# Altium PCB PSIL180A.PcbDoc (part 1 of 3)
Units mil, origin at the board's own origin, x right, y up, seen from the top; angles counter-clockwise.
Board outline 4350 x 4350 mil, 4 copper layers (L1-Top Layer, L2-GND, L3-GND/SIG, L4-Bottom Layer), stack 60.02 mil thick; 134 components, 52 nets, 287 pads, 1110 vias.
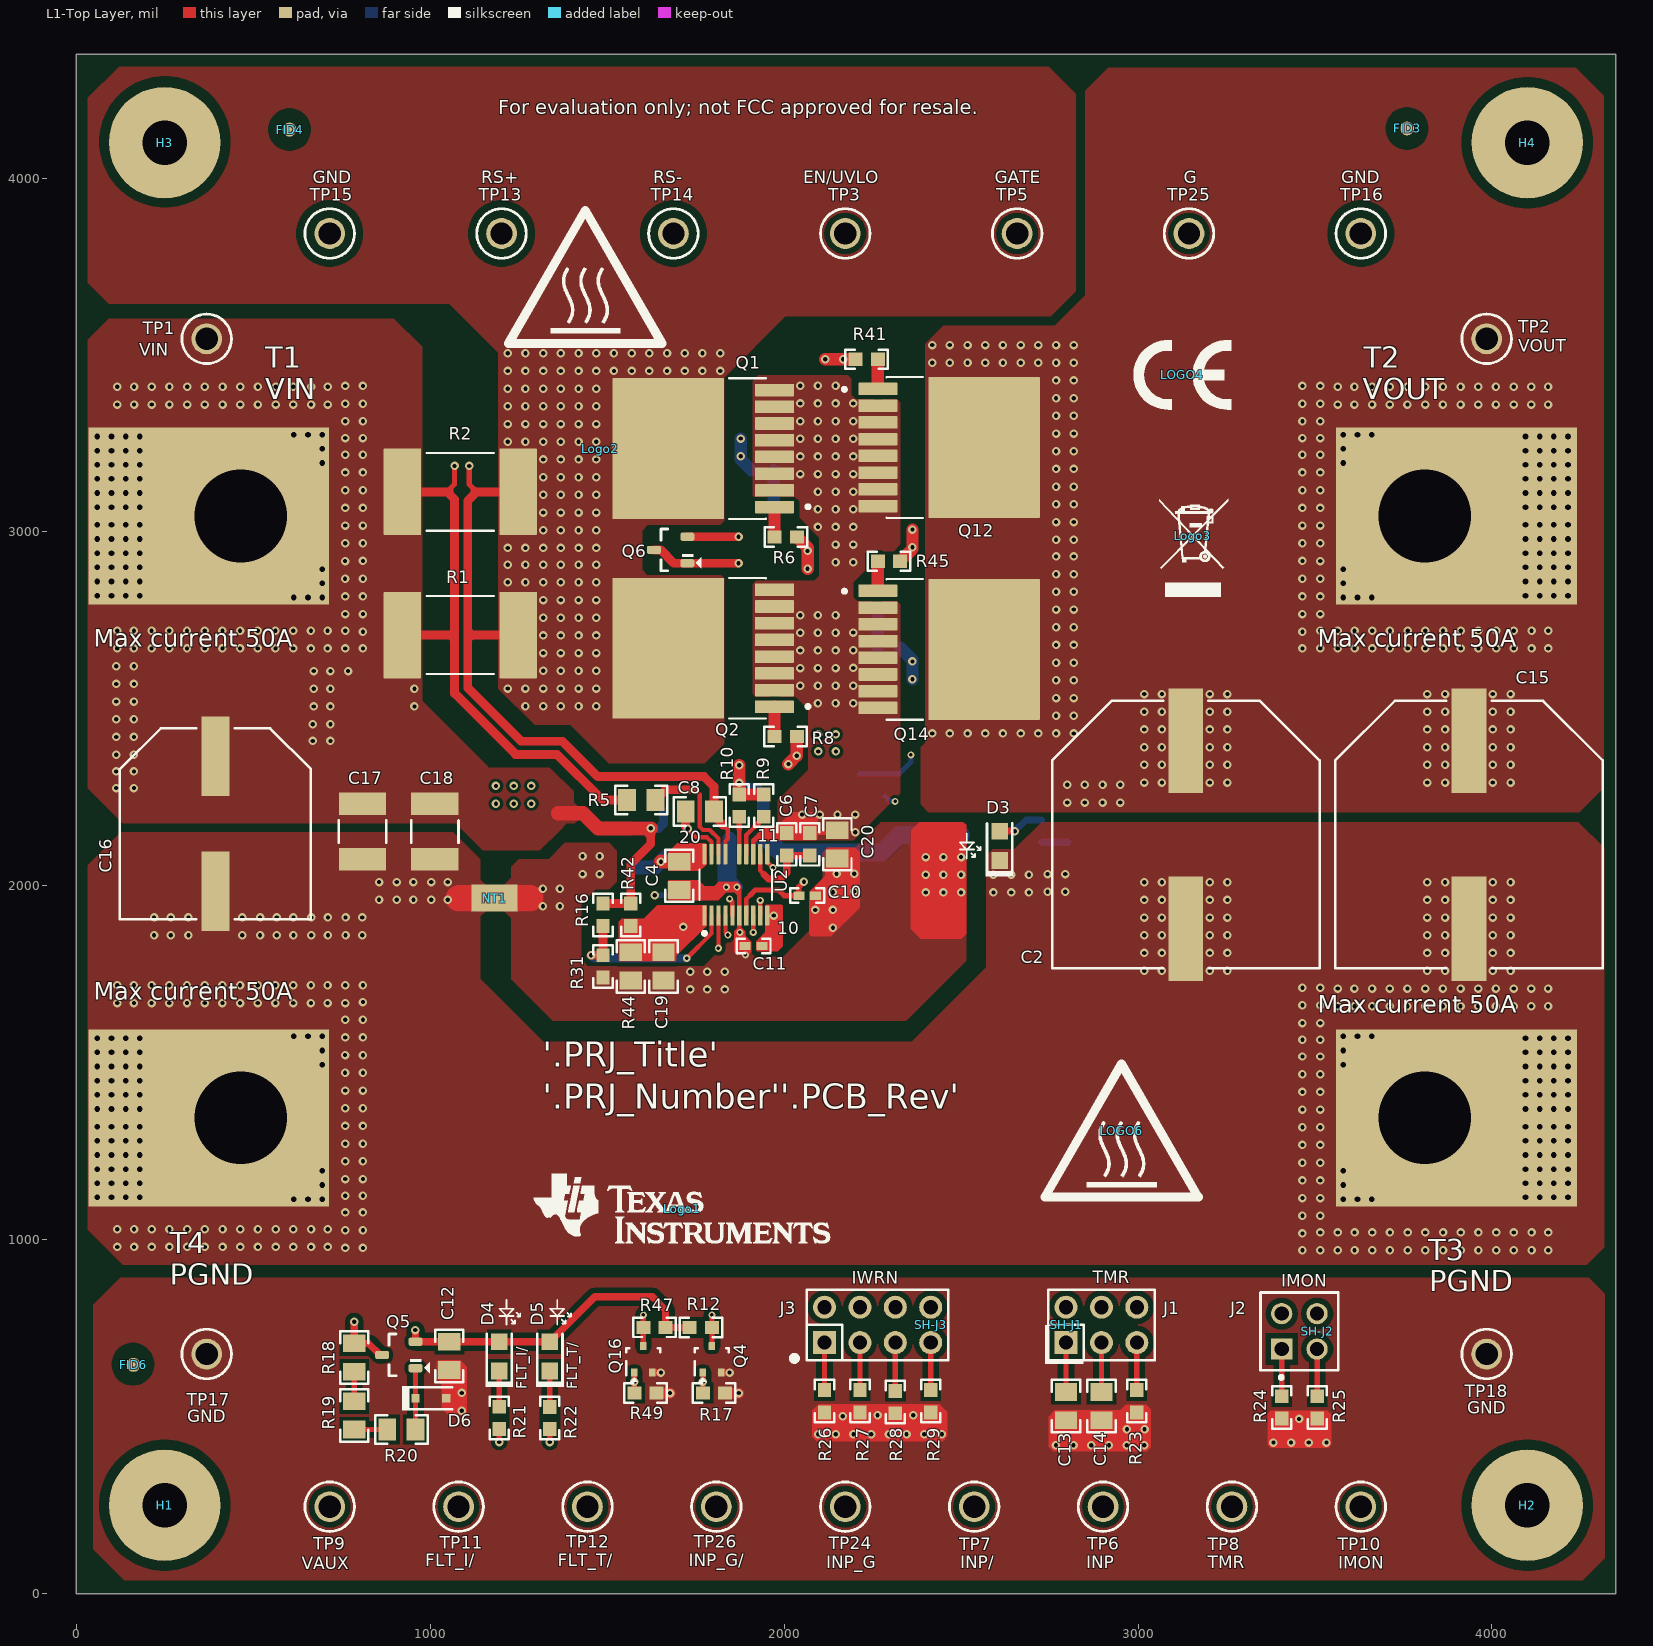
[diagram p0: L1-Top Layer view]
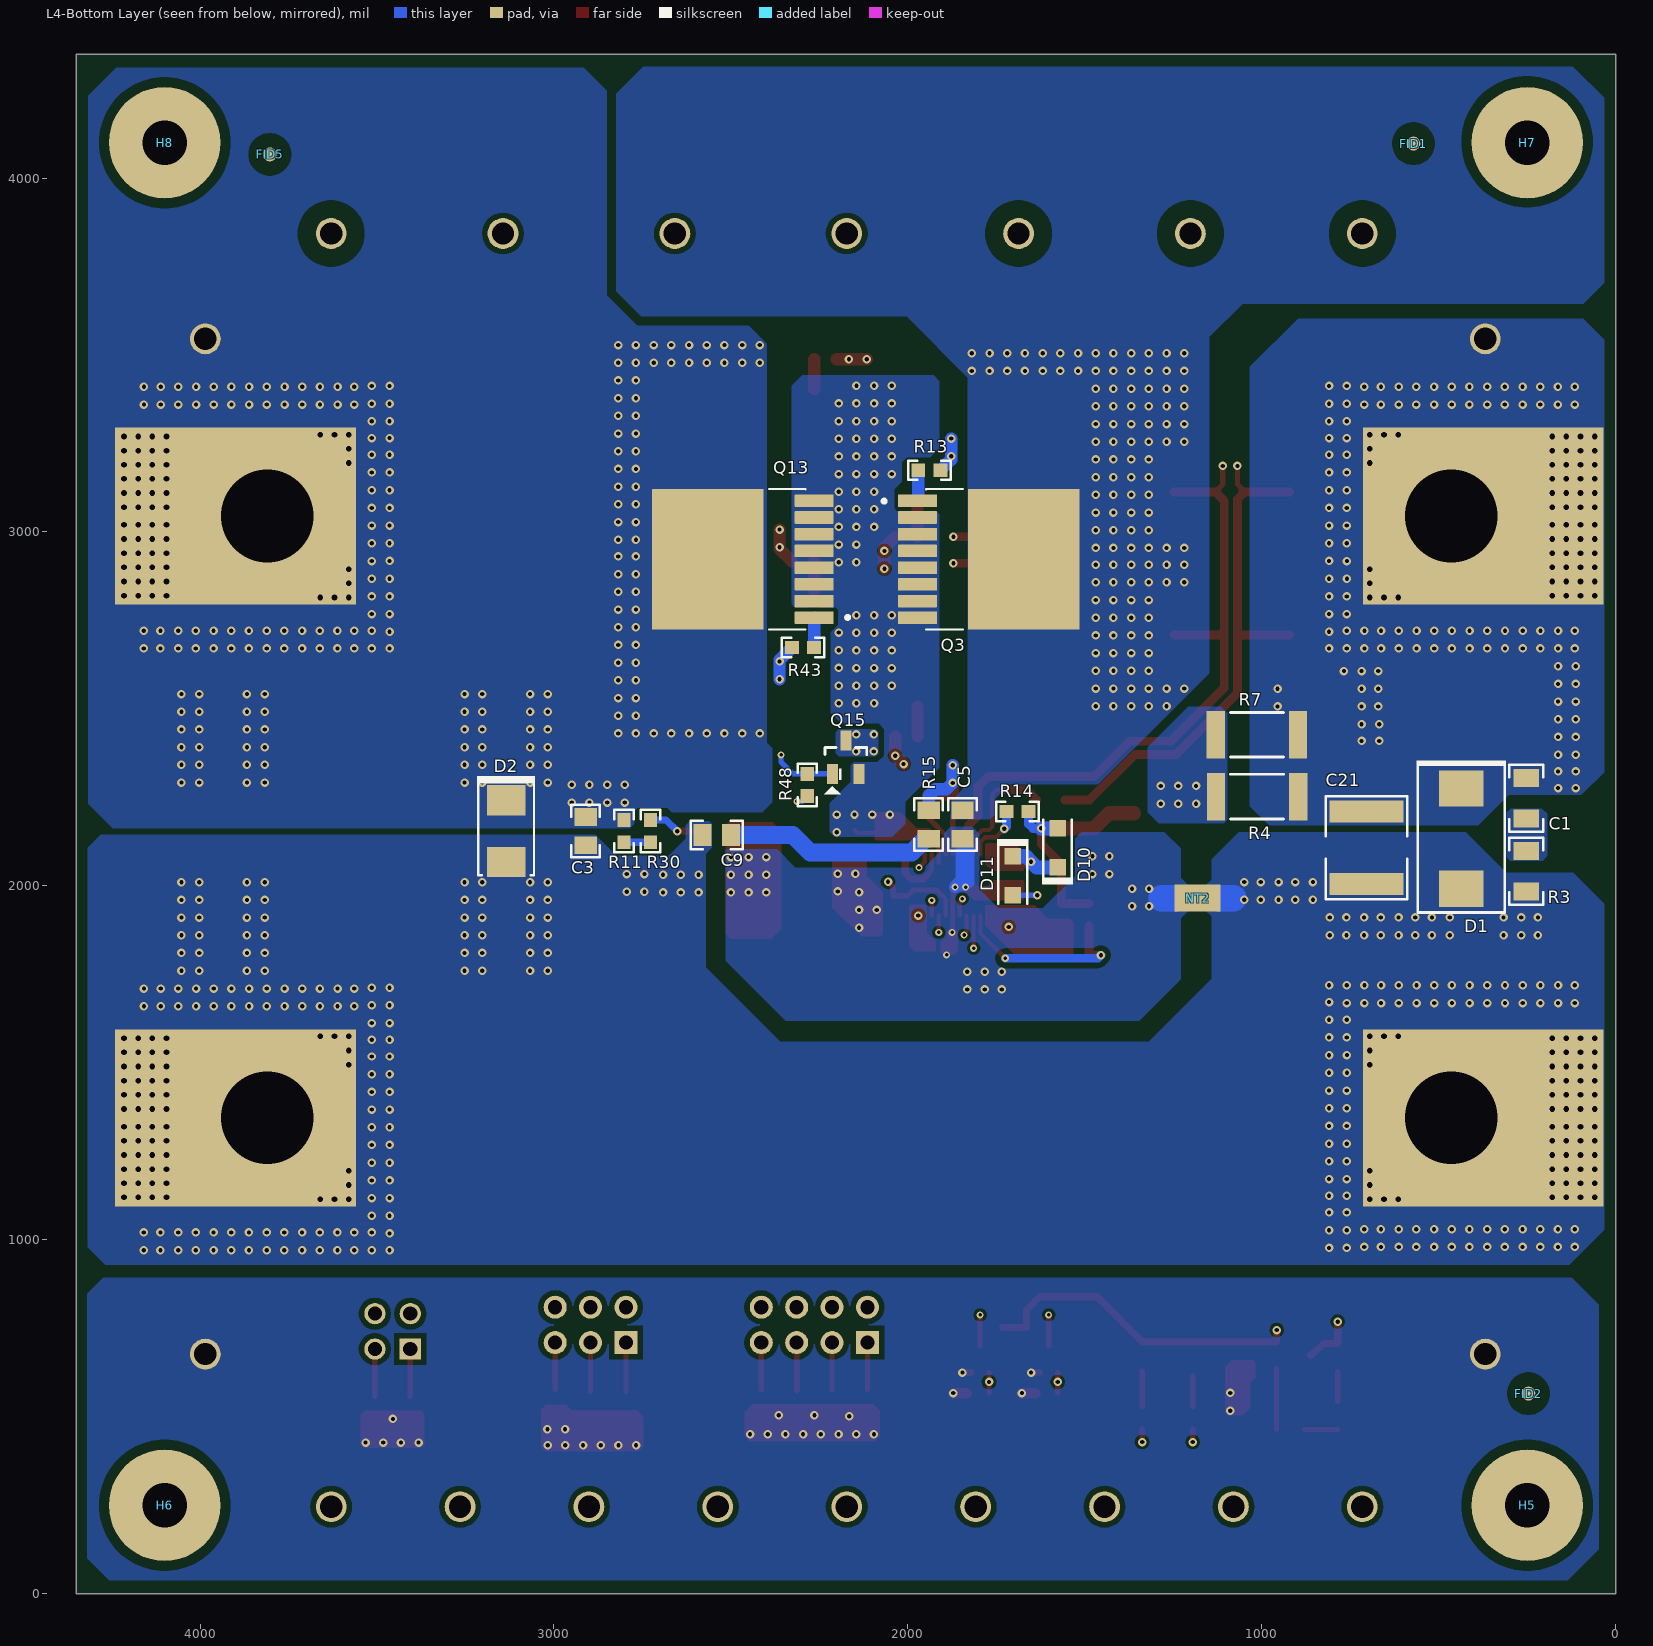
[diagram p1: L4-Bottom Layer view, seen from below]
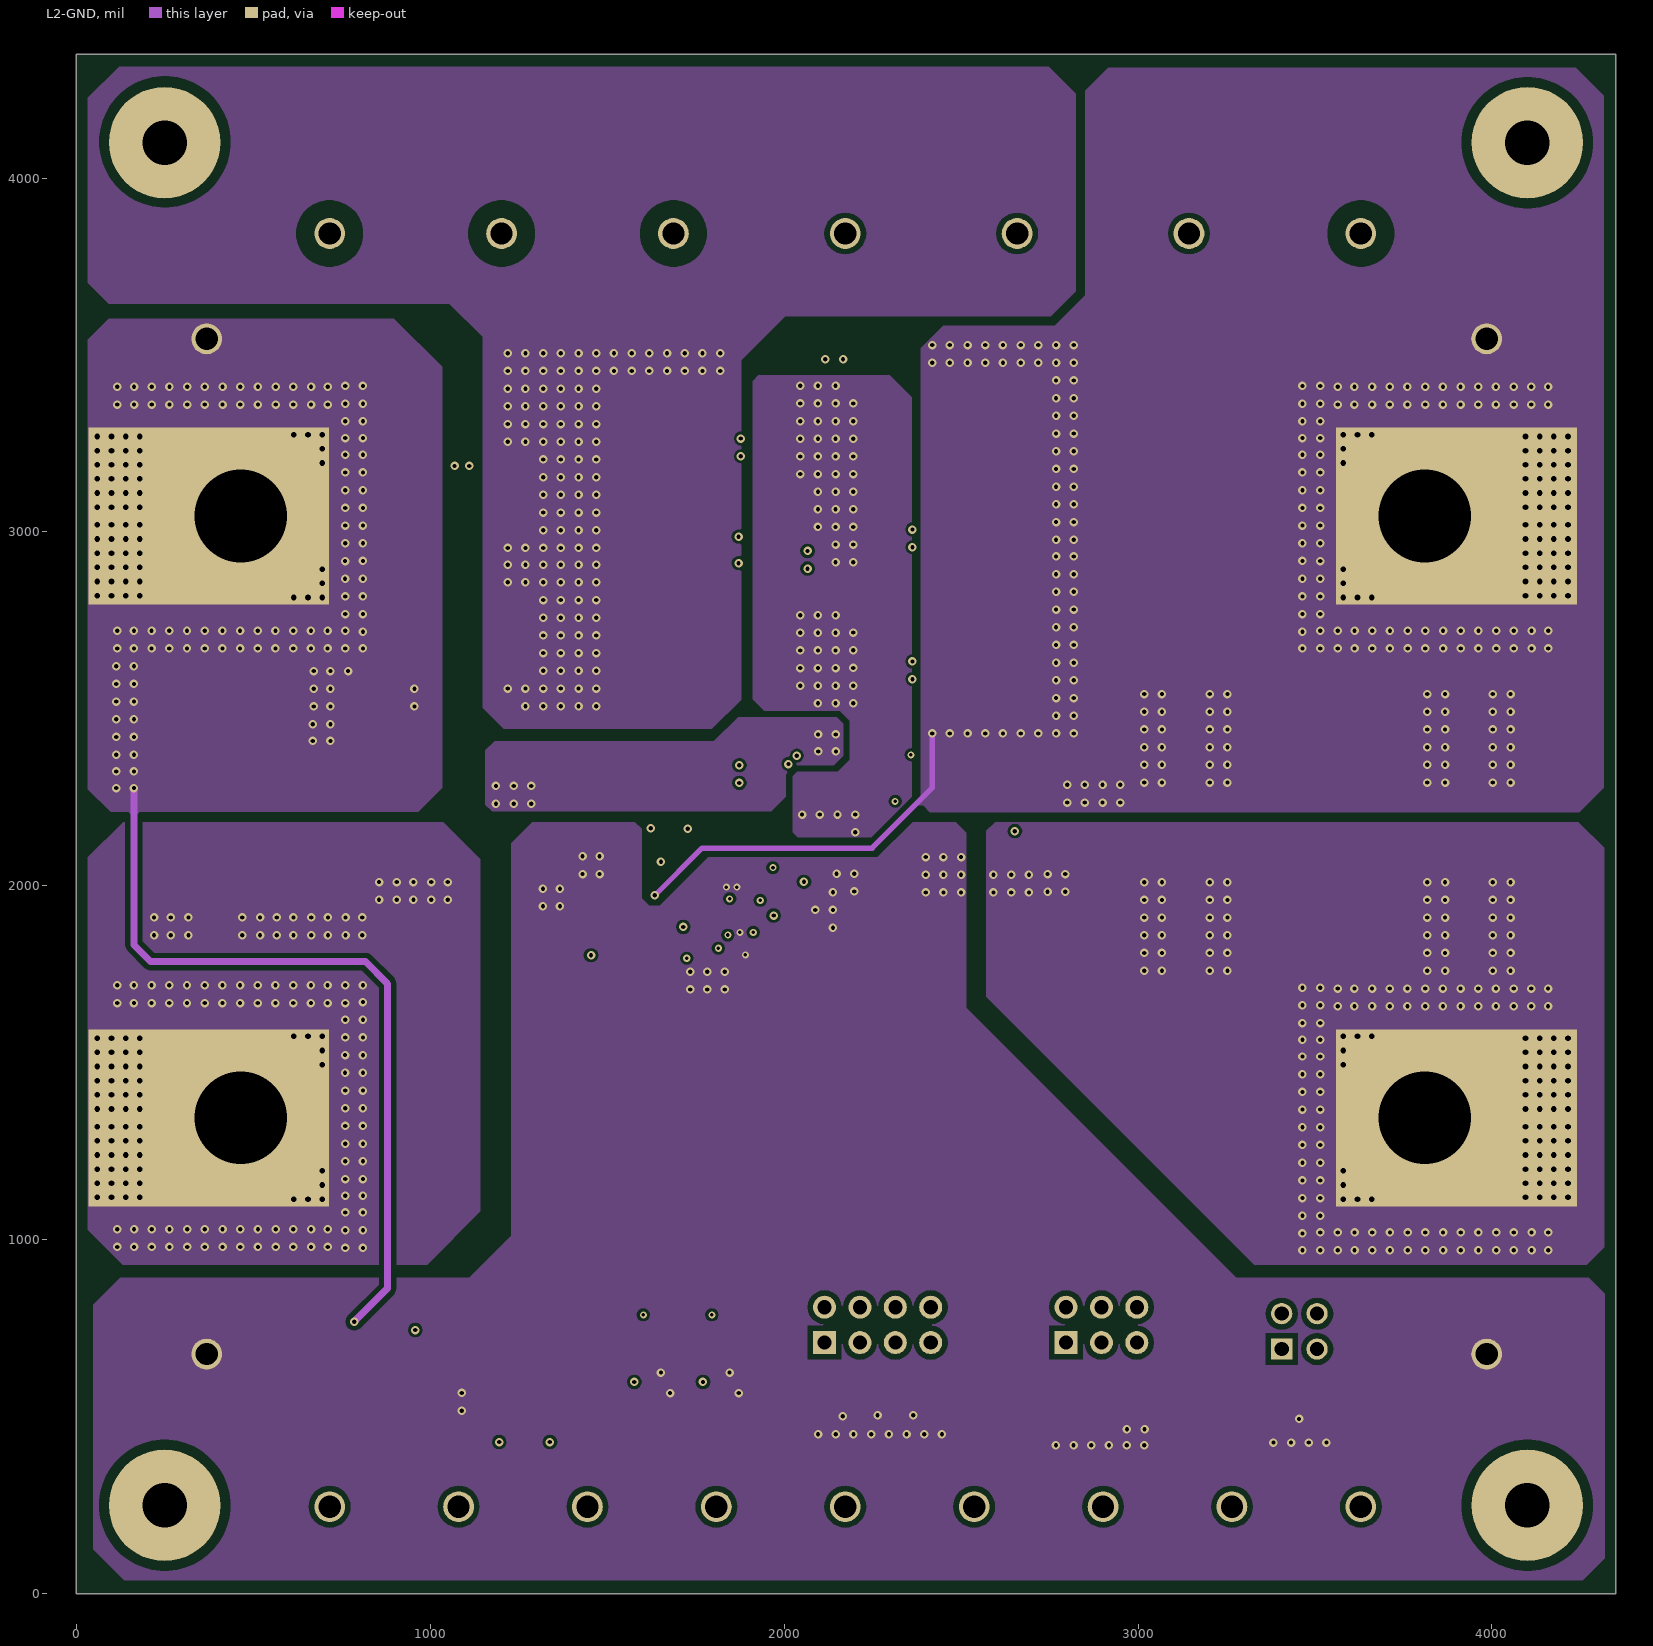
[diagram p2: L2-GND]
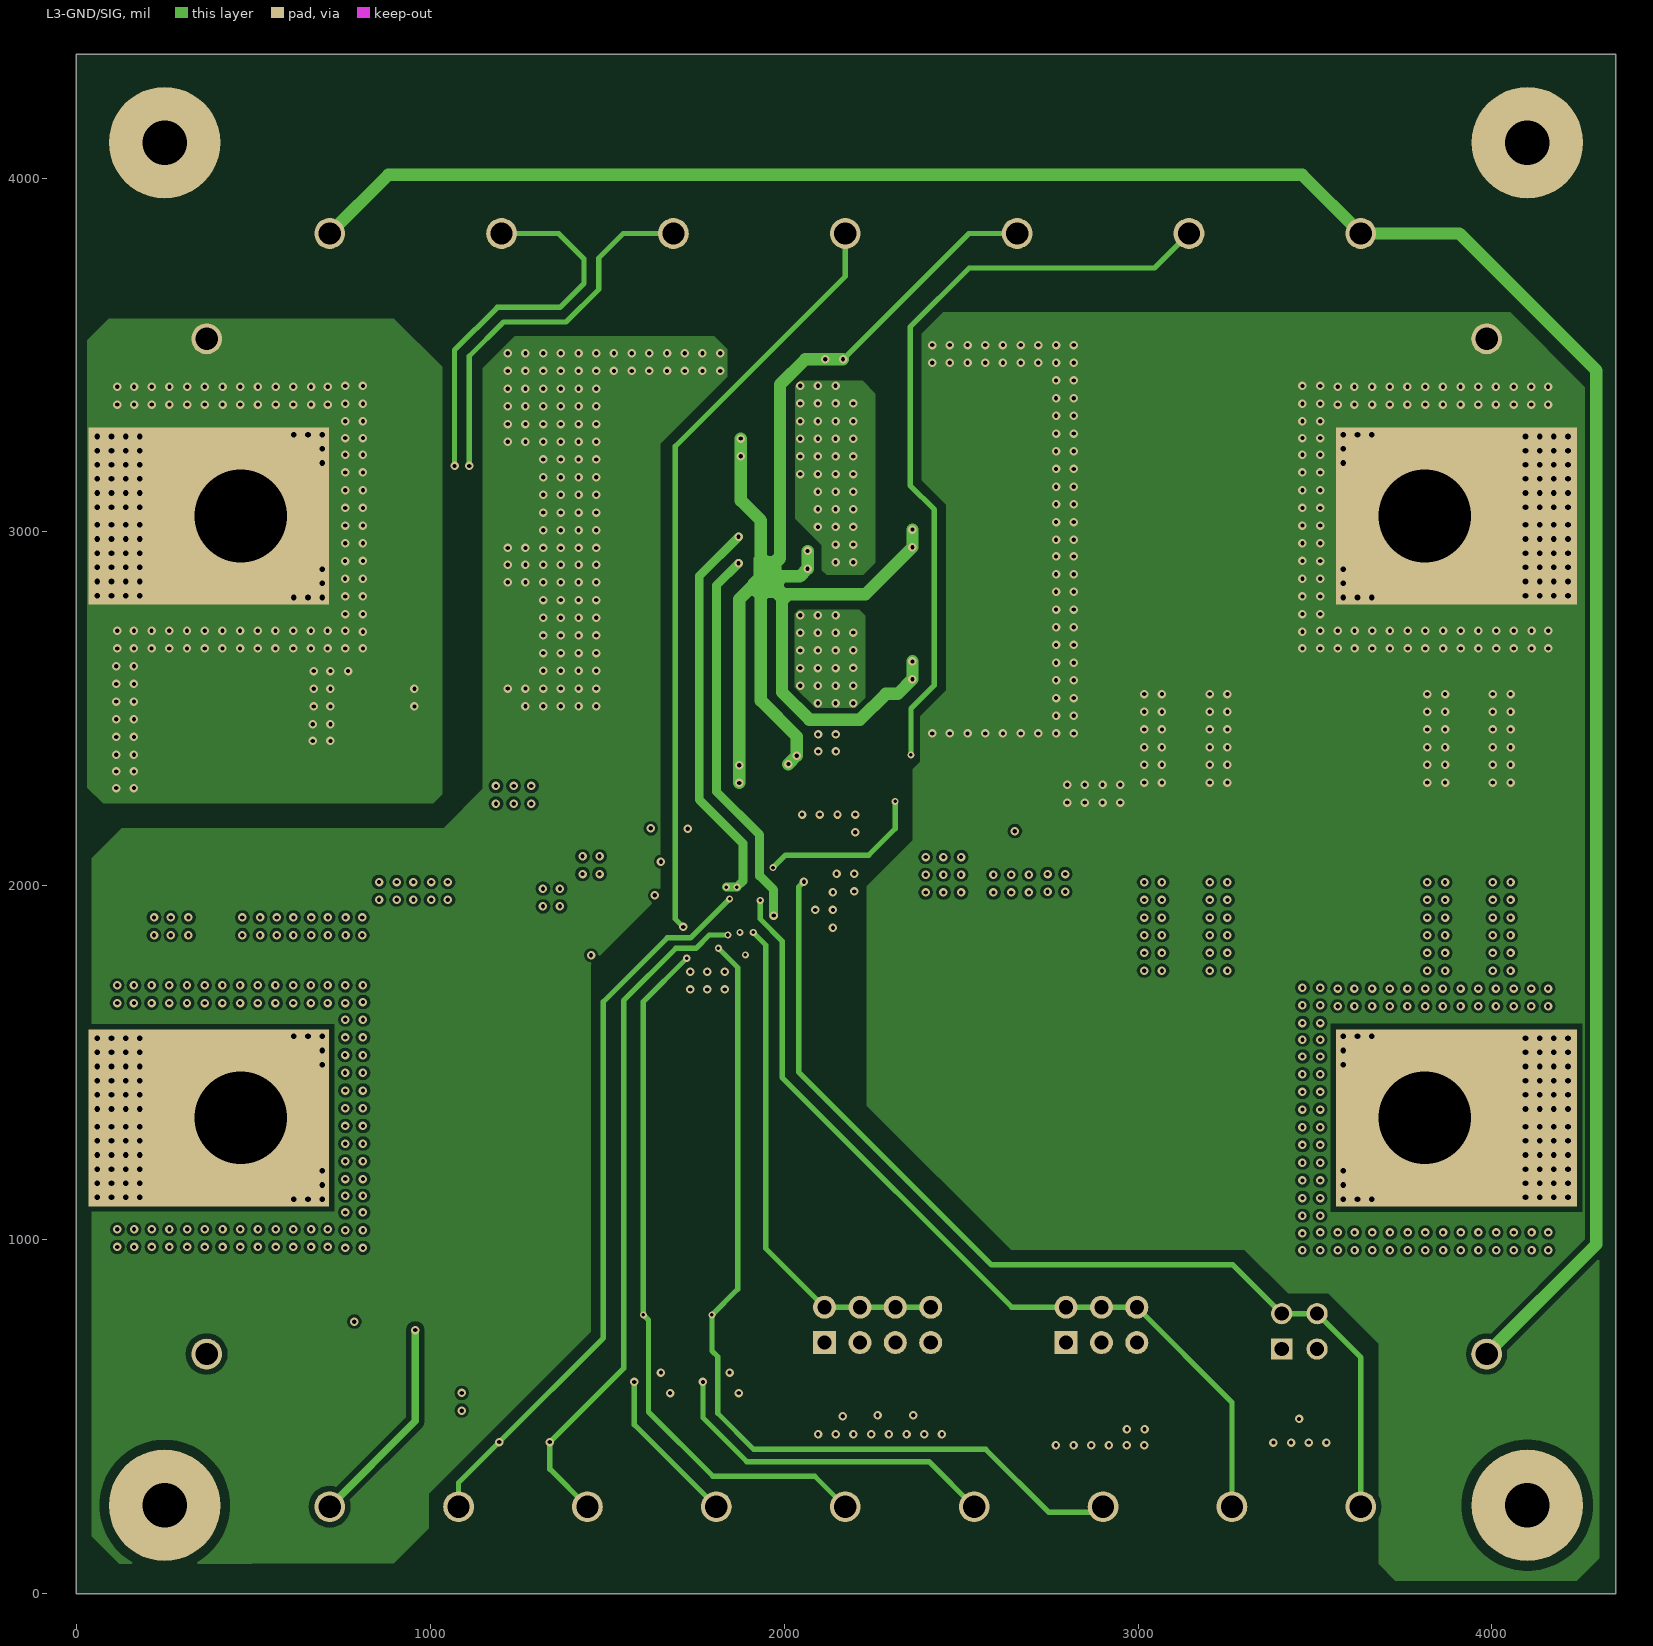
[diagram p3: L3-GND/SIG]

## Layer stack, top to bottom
Top Solder: solder mask 1, Solder Resist, Dk 3.5
L1-Top Layer: signal copper 2.756
Dielectric 1: prepreg 10.616, FR-4 High Tg, Dk 4.13
L2-GND: signal copper 2.638
Dielectric 2: core 28, FR-4 High Tg, Dk 4.53
L3-GND/SIG: signal copper 2.638
Dielectric 3: prepreg 10.616, FR-4 High Tg, Dk 4.13
L4-Bottom Layer: signal copper 2.756
Bottom Solder: solder mask 1, Solder Resist, Dk 3.5

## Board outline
0,0 4350,0 4350,4350 0,4350

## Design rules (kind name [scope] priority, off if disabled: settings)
AcuteAngle [All] p1: minimum=4.50000000000000E+0001 checktracksonly=FALSE
AssemblyTestPointUsage [All] p1: valid=2
Clearance [All] p1: gap=15 ignorepadtopadclearanceinfootprint=FALSE except(0: Arc-Text Track-Text SMDPad-Text THPad-Text Via-Text Fill-Text Poly-Text Region-Text Text-Text; 7.6: Track-Track Track-Region; 7.7: Track-SMDPad; 7.87: SMDPad-SMDPad SMDPad-Region Region-Region; 8: Via-Fill Via-Poly Via-Region; 8.4: SMDPad-Fill; 10: Arc-SMDPad Arc-Via Arc-Hole Track-Via Track-Hole SMDPad-Via SMDPad-Poly SMDPad-Hole THPad-Hole Via-Via Via-Hole Fill-Hole Poly-Hole Region-Hole Text-Hole; 11: Track-Fill)
ComponentClearance ComponentClearance_MountingHoles_FiducialMarks [InComponentClass('Mounting Holes') vs InComponentClass('FiducialMark')] p1: gap=5 collisioncheckmode=3 verticalgap=5 showdistances=FALSE
ComponentClearance ComponentClearance_Shunt [InComponentClass('Header') vs InComponentClass('Shunt')] p2: gap=0 collisioncheckmode=3 verticalgap=0 showdistances=FALSE
ComponentClearance ComponentClearance_Logo [InComponentClass('Logo')] p3: gap=5 collisioncheckmode=3 verticalgap=5 showdistances=FALSE
ComponentClearance ComponentClearance_ScrewToNut [(HasFootprint('NY PMS 440 0025 PH')) vs (HasFootprint('Keystone_1902C'))] p4: gap=5 collisioncheckmode=3 verticalgap=5 showdistances=FALSE
ComponentClearance ComponentClearance_MountingHoles [InComponentClass('Mounting Holes')] p5: gap=5 collisioncheckmode=3 verticalgap=100000 showdistances=FALSE
ComponentClearance ComponentClearance_SmallPassives [HasFootprint('0201*') or HasFootprint('0402*') or HasFootprint('0508') or HasFootprint('0603*') or HasFootprint('0612') or HasFootprint('0805*') or HasFootprint('0815*') or HasFootprint('0830*') or HasFootprint('1206*') or HasFootprint('1210*') or HasFootprint('1808*') or HasFootprint('1812*') or HasFootprint('1825*') or HasFootprint('2010*') or HasFootprint('2220*') or HasFootprint('2225*') or HasFootprint('2512*') or HasFootprint('2728*') or HasFootprint('3518*') vs HasFootprint('0201*') or HasFootprint('0402*') or HasFootprint('0508') or HasFootprint('0603*') or HasFootprint('0612') or HasFootprint('0805*') or HasFootprint('0815*') or HasFootprint('0830*') or HasFootprint('1206*') or HasFootprint('1210*') or HasFootprint('1808*') or HasFootprint('1812*') or HasFootprint('1825*') or HasFootprint('2010*') or HasFootprint('2220*') or HasFootprint('2225*') or HasFootprint('2512*') or HasFootprint('2728*') or HasFootprint('3518*')] p6: gap=5 collisioncheckmode=3 verticalgap=5 showdistances=FALSE
ComponentClearance ComponentClearance_THtoSMT [IsThruComponent vs IsSMTComponent] p7: gap=5 collisioncheckmode=3 verticalgap=5 showdistances=FALSE
ComponentClearance ComponentClearance_THtoTH [IsThruComponent vs IsThruComponent] p8: gap=5 collisioncheckmode=3 verticalgap=5 showdistances=FALSE
ComponentClearance [All] p9: gap=5 collisioncheckmode=3 verticalgap=5 showdistances=FALSE
DiffPairsRouting [All] p1: maxlimit=100 minlimit=10 mostfreqgap=10 toplayer_minwidth=15 toplayer_maxwidth=15 toplayer_prefwidth=15 midlayer1_minwidth=15 midlayer1_maxwidth=15 midlayer1_prefwidth=15 midlayer2_minwidth=15 midlayer2_maxwidth=15 midlayer2_prefwidth=15 bottomlayer_minwidth=15 bottomlayer_maxwidth=15 bottomlayer_prefwidth=15 maxuncoupledlength=1000
FabricationTestPointUsage TestPointUsage [All] p1: valid=2 allowmultiple=FALSE
FabricationTestpoint Testpoint [All] p1: side=3 testpointundercomponent=TRUE minsize=40 maxsize=100 preferedsize=60 minholesize=0 maxholesize=40 preferedholesize=32 testpointgrid=1 allowsidetop=TRUE allowsidebottom=TRUE usegrid=TRUE gridtolerance=0.01
FanoutControl Fanout_LCC [IsLCC] p1: bgadir=Out bgaviamode=Centered fanoutstyle=Auto fanoutdirection=Alternating viagrid=1 // Fanout_LCC (Default Rule)
FanoutControl Fanout_BGA [IsBGA] p2: bgadir=Out bgaviamode=Centered fanoutstyle=Auto fanoutdirection=Alternating viagrid=1 // Fanout_BGA (Default Rule)
FanoutControl Fanout_Default [All] p4: bgadir=Out bgaviamode=Centered fanoutstyle=Auto fanoutdirection=Alternating viagrid=1 // Fanout_Default (Default Rule)
FanoutControl Fanout_Small [(CompPinCount < 5)] p5: bgadir=Out bgaviamode=Centered fanoutstyle=Auto fanoutdirection=OutThenIn viagrid=1 // Fanout_Small (Default Rule)
HoleSize [All] p1: absolutevalues=TRUE maxlimit=500 minlimit=7.87 maxpercent=80.000 minpercent=20.000
MinimumAnnularRing MinimumAnnularRing_ThermalPadVias [IsVia and InAnyComponent] p1: minimumring=5.91
MinimumAnnularRing [All] p2: minimumring=5
MinimumSolderMaskSliver MinimumSolderMaskSliver_Logo [InComponentClass('Logo') vs InComponentClass('Logo')] p1: minsoldermaskwidth=0.7
MinimumSolderMaskSliver [All] p2: minsoldermaskwidth=3.94
PlaneConnect [All] p1: planeconnectstyle=Direct reliefexpansion=10 reliefentries=4 reliefconductorwidth=10 reliefairgap=10
PolygonConnect [All] p1: connectstyle=Direct reliefconductorwidth=10 reliefentries=4 polygonreliefangle="90 Angle" airgapwidth=10
RoutingLayers [All] p1: top layer_v5=TRUE mid layer 1_v5=FALSE mid layer 2_v5=FALSE bottom layer_v5=TRUE
RoutingVias ThermalPadVias [IsVia and InAnyComponent] p1: holewidth=10 width=20 viastyle="Through Hole" minholewidth=7.87 minwidth=19.68 maxholewidth=30 maxwidth=50
RoutingVias [All] p2: holewidth=12 width=24 viastyle="Through Hole" minholewidth=8 minwidth=16 maxholewidth=30 maxwidth=50
SilkToBoardRegionClearance [Not ((IsComment or IsDesignator) And (Hide <> 'False')) and not InRegion(1000,500,4000,800)] p1:
SilkToSilkClearance SilkToSilkClearance_Pb-FreeLogo [(HasFootprint('Pb-Free_Overlay_Medium') OR HasFootprint('Pb-Free_Overlay_Small')) vs (HasFootprint('Pb-Free_Overlay_Medium') OR HasFootprint('Pb-Free_Overlay_Small'))] p1: silktosilkclearance=1
SilkToSilkClearance [All] p2: silktosilkclearance=1
SilkToSolderMaskClearance SilkToComponentPadClearance [(IsPad or IsFill or IsRegion) and InAnycomponent] p1: minsilkscreentomaskgap=1 clearancetoexposedcopper=TRUE
SilkToSolderMaskClearance "Silk to Solder Mask Opening" [All] p2: minsilkscreentomaskgap=1 clearancetoexposedcopper=FALSE
SolderMaskExpansion [All] p1: expansion=1.97
UnRoutedNet [All] p1: checkbadconnections=TRUE
Width [All] p1: maxlimit=100 minlimit=8 preferedwidth=15 checkconnectedcopper=TRUE
13 further rules are at their usual default settings.

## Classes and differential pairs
component class "Mounting Holes": H1 H2 H3 H4
component class Shunt: SH-J1 SH-J2 SH-J3
component class AssemblyNote: ZZ1 ZZ2 ZZ3
component class FiducialMark: FID1 FID2 FID3 FID4 FID5 FID6
component class PSIL180E1_Hardware: FID1 FID2 FID3 FID4 FID5 FID6 H1 H2 H3 H4 H5 H6 H7 H8 H9 H10 H11 H12 Logo1 Logo2 Logo3 LOGO4 LOGO6 SH-J1 SH-J2 SH-J3 ZZ1 ZZ2 ZZ3
component class Logo: Logo1
component class PSIL180E1: C1 C2 C3 C4 C5 C6 C7 C8 C9 C10 C11 C12 C13 C14 C15 C16 C17 C18 C19 C20 C21 D1 D2 D3 D4 D5 D6 D10 D11 J1 J2 J3 NT1 NT2 Q1 Q2 Q3 Q4 Q5 Q6 Q12 Q13 Q14 Q15 Q16 R1 R2 R3 R4 R5 R6 R7 R8 R9 R10 R11 R12 R13 R14 R15 R16 R17 R18 R19 R20 R21 R22 R23 R24 R25 R26 R27 R28 R29 R30 R31 R41 R42 R43 R44 R45 R47 R48 R49 T1 T2 T3 T4 TP1 TP2 TP3 TP5 TP6 TP7 TP8 TP9 TP10 TP11 TP12 TP13 TP14 TP15 TP16 TP17 TP18 TP24 TP25 TP26 U2
component class Header: J1 J2 J3

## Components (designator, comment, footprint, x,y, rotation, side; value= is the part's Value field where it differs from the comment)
C1 "12061C103KAT2A" 1206 252.9,2248.09 r270 bottom value=0.01uF
C2 "EEV-FK2A221M" SM_RADIAL_K16 3135,2145 r270 top value=220uF
C3 "CGA4J2X7R2A104K125AA" 0805_HV 2910.59,2155 r270 bottom value=0.1uF
C4 "CGA4J2X7R2A104K125AA" 0805_HV 1703.7,2028.68 r270 top value=0.1uF
C5 "CGA4J2X7R2A104K125AA" 0805_HV 1845.82,2173.72 r270 bottom value=0.1uF
C6 "CGA3E3X7R1E474K080AB" 0603 2007.62,2117.74 r90 top value=0.47uF
C7 "CGA3E3X7R1E474K080AB" 0603 2072.41,2117.74 r90 top value=0.47uF
C8 "C0805C102J5RACTU" 0805_HV 1761.93,2210.36 r0 top value=1000pF
C9 "CGA4J2X7R2A104K125AA" 0805_HV 2540.16,2143.83 r0 bottom value=0.1uF
C10 "GRM155R71H331KA01D" 0402 2065.52,1972.38 r0 top value=330pF
C11 "0402ZC102KAT2A" 0402 1913.67,1830.25 r180 top value=1000pF
C12 "GCM21BR71E225KA73L" 0805_HV 1054.26,672.3 r270 top value=2.2uF
C13 "C0805C683K1RACTU" 0805_HV 2796.71,530.25 r270 top value=0.068uF
C14 "C0805C684K5RACTU" 0805_HV 2896.71,530.25 r270 top value=0.68uF
C15 "EEV-FK2A221M" SM_RADIAL_K16 3935,2145 r270 top value=220uF
C16 "EEV-FK2A470Q" SM_RADIAL_H13 393.37,2175.58 r270 top value=47uF
C17 "C4532X7R2A105K230KA" 1812_254 808.94,2153.79 r270 top value=1uF
C18 "C4532X7R2A105K230KA" 1812_254 1013.59,2153.79 r270 top value=1uF
C19 "08051C103JAT2A" 0805_HV 1659.54,1772.58 r270 top value=0.01uF
C20 "CGA4J2X7R2A104K125AA" 0805_HV 2150.57,2117.74 r270 top value=0.1uF
C21 "22201C106MAT2A" 2220_280 704.48,2108.1 r270 bottom value=10uF
D1 "SMCJ70A" SMC_265 436.85,2133.52 r270 bottom value=70V
D2 "SS2H10-E3/5BT" SMB 3135,2155 r270 bottom value=100V
D3 "LTST-C170KGKT" LTST-C170KGKT_Green 2609.11,2113.45 r270 top value=Green
D4 "LTST-C170KRKT" LED_LTST-C170_Red 1195.28,670.96 r270 top value=Red
D5 "LTST-C170KRKT" LED_LTST-C170_Red 1338.31,670.96 r270 top value=Red
D6 "SZMM3Z5V6ST1G" SOD-323 1002.09,552.51 r0 top value=5.6V
D10 "BAT46WH,115" SOD-123F 1577.02,2107.55 r90 bottom value=100V
D11 "BAT46WH,115" SOD-123F 1703.7,2028.68 r270 bottom value=100V
FID1 "Fiducial" Fiducial10-20 571.68,4097.21 r180 bottom
FID2 "Fiducial" Fiducial10-20 246.92,565.59 r0 bottom
FID3 "Fiducial" Fiducial10-20 3760.04,4140.03 r270 top
FID4 "Fiducial" Fiducial10-20 602.83,4137.04 r0 top
FID5 "Fiducial" Fiducial10-20 3802.99,4066.92 r90 bottom
FID6 "Fiducial" Fiducial10-20 161.94,647.06 r180 top
H1 "NY PMS 440 0025 PH" "NY PMS 440 0025 PH" 250,250 r0 top
H2 "NY PMS 440 0025 PH" "NY PMS 440 0025 PH" 4100,250 r0 top
H3 "NY PMS 440 0025 PH" "NY PMS 440 0025 PH" 250,4100 r0 top
H4 "NY PMS 440 0025 PH" "NY PMS 440 0025 PH" 4100,4100 r0 top
H5 "1902C" Keystone_1902C 250,250 r180 bottom
H6 "1902C" Keystone_1902C 4100,250 r180 bottom
H7 "1902C" Keystone_1902C 250,4100 r180 bottom
H8 "1902C" Keystone_1902C 4100,4100 r180 bottom
J1 "PEC03DAAN" SULLINS_PEC03DAAN 2896.71,759.71 r0 top
J2 "PEC02DAAN" Sullins_PEC02DAAN 3455.91,741.54 r90 top
J3 "PEC04DAAN" CONN_PEC04DAAN 2264.43,759.71 r0 top
Logo1 "Texas Instruments" TI_Stacked_Overlay_Small 1711.85,1088.02 r0 top
Logo2 "FCC disclaimer" FCC_disclaimer 1480.43,3234.9 r0 top
Logo3 "WEEE logo" WEEE_Minimum 3155.03,2989.08 r0 top
LOGO4 "CE Mark" CE_Mark_5mm 3125.05,3443.88 r0 top
LOGO6 "CAUTION HOT SURFACE" IEC_HotSurface_Medium 2953.57,1308.4 r0 top
NT1 "NETTIE-SMT2-W0.8L3.3(MM)" NETTIE-SMT2-W0.8L3.3(MM) 1191.38,1965.49 r0 top net-tie
NT2 "NETTIE-SMT2-W0.8L3.3(MM)" NETTIE-SMT2-W0.8L3.3(MM) 1191.38,1965.97 r0 bottom net-tie
Q1 "IAUS300N08S5N012ATMA1" FP-IAUS300N08S5N012ATMA1_HSOG-8-MFG 1776.11,3235.65 r90 top
Q2 "IAUS300N08S5N012ATMA1" FP-IAUS300N08S5N012ATMA1_HSOG-8-MFG 1776.11,2671.39 r90 top
Q3 "IAUS300N08S5N012ATMA1" FP-IAUS300N08S5N012ATMA1_HSOG-8-MFG 1776.11,2922.89 r270 bottom
Q4 "2N7002W-7-F" SOT-323 1796.32,662.66 r90 top value=60V
Q5 "PMBT5551,215" SOT-23#1 911.54,674.9 r180 top value="160 V"
Q6 "MMBT3904" SOT-23#1 1679.54,2949.3 r180 top value="40 V"
Q12 "IAUS300N08S5N012ATMA1" FP-IAUS300N08S5N012ATMA1_HSOG-8-MFG 2461.7,3238.73 r270 top
Q13 "IAUS300N08S5N012ATMA1" FP-IAUS300N08S5N012ATMA1_HSOG-8-MFG 2461.7,2922.89 r90 bottom
Q14 "IAUS300N08S5N012ATMA1" FP-IAUS300N08S5N012ATMA1_HSOG-8-MFG 2461.7,2668.3 r270 top
Q15 "DMN10H220L-7" SOT-23#2 2175.35,2363.82 r90 bottom value=100V
Q16 "2N7002W-7-F" SOT-323 1602.45,662.66 r90 top value=60V
R1 "WSL3921L5000FEA" FP-WSL3921L5000FEA_3921-MFG 1085.17,2708.74 r0 top value=500µ
R2 "WSL3921L5000FEA" FP-WSL3921L5000FEA_3921-MFG 1085.17,3113.48 r0 top value=500µ
R3 "CRCW1206100RFKEAHP" 1206 252.9,2041.44 r90 bottom value=100
R4 "CRCW2512220RFKEG" 2512 1013.54,2252.37 r0 bottom value=220
R5 "CRCW0805100RFKEA" 0805_HV 1596.51,2242.81 r180 top value=100
R6 "RC0603FR-072R21L" 0603 2005.08,2985.85 r180 top value=2.21
R7 "CRCW2512220RFKEG" 2512 1014.08,2426.92 r0 bottom value=220
R8 "RC0603FR-072R21L" 0603 2004.46,2422.22 r180 top value=2.21
R9 "CRCW06030000Z0EA" 0603 1942.83,2227 r90 top value=0
R10 "CRCW060310R0FKEAHP" 0603 1873.58,2227 r90 top value=10.0
R11 "RC0603FR-079K53L" 0603 2802.09,2155 r90 bottom value=9.53k
R12 "CRCW06033K16FKEA" 0603 1764.83,752.8 r180 top value=3.16k
R13 "CRCW06030000Z0EA" 0603 1939.47,3174.49 r0 bottom value=0
R14 "RT0603BRD071K47L" 0603 1690.44,2210.36 r0 bottom value=1.47k
R15 "RC0805FR-0710RL" 0805_HV 1941.55,2173.72 r90 bottom value=10.0
R16 "RC0603FR-07470KL" 0603 1488.81,1918.4 r90 top value=470k
R17 "RC0603FR-079K53L" 0603 1802.23,567.18 r180 top value=9.53k
R18 "ERJ-6ENF1002V" 0805_HV 785.75,667.59 r90 top value=10.0k
R19 "ERJ-6ENF1002V" 0805_HV 785.75,504.21 r90 top value=10.0k
R20 "ERJ-6ENF1002V" 0805_HV 918.78,464.21 r180 top value=10.0k
R21 "CRCW06033K16FKEA" 0603 1195.28,497.06 r90 top value=3.16k
R22 "CRCW06033K16FKEA" 0603 1338.31,496.81 r90 top value=3.16k
R23 "CRCW0603100KFKEA" 0603 2996.71,544.27 r90 top value=100k
R24 "RC0603FR-0741K2L" 0603 3406.32,526.64 r90 top value=41.2k
R25 "RT0603DRE0720KL" 0603 3506.32,526.64 r90 top value=20.0k
R26 "ERJ-3GEY0R00V" 0603 2114.43,544.27 r270 top value=0
R27 "RC0603FR-07475KL" 0603 2214.47,544.27 r90 top value=475k
R28 "CRCW0603158KFKEA" 0603 2314.43,541.65 r90 top value=158k
R29 "CRCW060347K0FKEA" 0603 2414.43,544.27 r90 top value=47.0k
R30 "RC0603FR-079K53L" 0603 2727.18,2155 r270 bottom value=9.53k
R31 "RC0603FR-079K53L" 0603 1488.81,1772.73 r90 top value=9.53k
R41 "RC0603FR-072R21L" 0603 2233.35,3487.9 r0 top value=2.21
R42 "RC0603FR-07470KL" 0603 1566.93,1918.4 r90 top value=470k
R43 "CRCW06030000Z0EA" 0603 2296.35,2673.72 r180 bottom value=0
R44 "CRCW080524K9FKEA" 0805_HV 1566.93,1772.58 r90 top value=24.9k
R45 "RC0603FR-072R21L" 0603 2296.35,2917.47 r180 top value=2.21
R47 "CRCW06033K16FKEA" 0603 1633.95,752.8 r0 top value=3.16k
R48 "ERJ-3GEY0R00V" 0603 2284.44,2285.08 r270 bottom value=0
R49 "RC0603FR-079K53L" 0603 1608.36,567.18 r180 top value=9.53k
SH-J1 "Shunt" SPC02SYAN 2796.71,759.71 r270 top value=1x2
SH-J2 "Shunt" SPC02SYAN 3505.91,741.54 r90 top value=1x2
SH-J3 "Shunt" SPC02SYAN 2414.42,759.71 r90 top value=1x2
T1 "CB70-14-CY" CB70-14-CY 465,3045 r0 top locked
T2 "CB70-14-CY" CB70-14-CY 3810,3045 r180 top locked
T3 "CB70-14-CY" CB70-14-CY 3810,1345 r180 top locked
T4 "CB70-14-CY" CB70-14-CY 465,1345 r0 top locked
TP1 "VIN" Keystone5010 368.66,3545.63 r0 top
TP2 "VOUT" Keystone5010 3985,3545.63 r0 top
TP3 "EN/UVLO" Keystone5012 2172.92,3843.34 r270 top
TP5 "GATE" Keystone5012 2658.48,3843.34 r0 top
TP6 "INP" Keystone5012 2901.26,246.13 r0 top
TP7 "INP/" Keystone5013 2537.09,246.13 r0 top
TP8 "TMR" Keystone5012 3265.43,246.13 r0 top
TP9 "VAUX" Keystone5010 716.24,246.13 r0 top
TP10 "IMON" Keystone5012 3629.6,246.13 r0 top
TP11 "FLT_I/" Keystone5012 1080.41,246.13 r0 top
TP12 "FLT_T/" Keystone5012 1444.58,246.13 r0 top
TP13 "RS+" Keystone5012 1201.8,3843.34 r0 top
TP14 "RS-" Keystone5012 1687.36,3843.34 r0 top
TP15 "GND" Keystone5011 716.24,3843.34 r0 top
TP16 "GND" Keystone5011 3629.6,3843.34 r0 top
TP17 "GND" Keystone5011 368.66,677.5 r0 top
TP18 "GND" Keystone5011 3985,677.5 r0 top
TP24 "INP_G" Keystone5012 2172.92,246.13 r0 top
TP25 "G" Keystone5012 3144.04,3843.34 r0 top
TP26 "INP_G/" Keystone5013 1808.75,246.13 r0 top
U2 "PTPS48111-Q1" 0-MFG 1863.74,2003.01 r90 top
ZZ1 "These assemblies are ESD sensitive, ESD precautions shall be observed." AssemblyNote 262.99,5787.3 r0 top
ZZ2 "These assemblies must be clean and free from flux and all contaminants. Use of no clean flux is not acceptable." AssemblyNote 262.99,5567.3 r0 top
ZZ3 "These assemblies must comply with workmanship standards IPC-A-610 Class 2, unless otherwise specified." AssemblyNote 262.99,5687.3 r0 top

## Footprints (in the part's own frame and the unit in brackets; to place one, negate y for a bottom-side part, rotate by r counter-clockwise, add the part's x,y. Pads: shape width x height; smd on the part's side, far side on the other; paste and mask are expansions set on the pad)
0-MFG [mm]
  rrect33% 1.45x0.3 smd paste+0 mask+0: 1(-2.2,2.25) 2(-2.2,1.75) 3(-2.2,1.25) 4(-2.2,0.75) 5(-2.2,0.25) 6(-2.2,-0.25) 7(-2.2,-0.75) 8(-2.2,-1.25) 9(-2.2,-1.75) 10(-2.2,-2.25) 11(2.2,-2.25) 12(2.2,-1.75) 13(2.2,-1.25) 14(2.2,-0.75) 15(2.2,-0.25) 17(2.2,0.75) 18(2.2,1.25) 19(2.2,1.75) 20(2.2,2.25)
  silkscreen extent -3.6,-2.6 1.1,2.6, body extent -3.03,-2.85 3.03,2.85, height 0.25
0402 [mm] "0402 from SM-752 data"
  rect 0.8x0.6 smd: 1(-0.6,0) 2(0.6,0)
  silkscreen extent -1.22,-0.52 1.22,0.52, body extent -0.55,-0.3 0.55,0.3, height 0.6
0603 [mm] "0603 from SM-752 data"
  rect 1x0.95 smd: 1(-0.8,0) 2(0.8,0)
  silkscreen extent -1.52,-0.69 1.52,0.69, body extent -0.87,-0.47 0.87,0.47, height 1
0805_HV [mil] "0805 with 30mil clearance between pads"
  rect 50x63 smd: 1(-40,0) 2(40,0)
  silkscreen extent -74,-40 74,40, body extent -43,-29 43,29, height 57
1206 [mm] "1206 from SM-752 data"
  rect 1.3x1.85 smd: 1(-1.45,0) 2(1.45,0)
  silkscreen extent -2.4,-1.21 2.4,1.21, body extent -1.7,-0.9 1.7,0.9, height 1.35
1812_254 [mm] "SMD, 2-Leads, Body 4.8x3.4mm"
  rect 1.6x3.4 smd: 1(-2,0) 2(2,0)
  silkscreen extent -0.8,-1.7 0.8,1.7, body extent -2.4,-1.7 2.4,1.7, height 2.54
2220_280 [mm] "Chip Capacitor, Body 5.7x5.0mm, IPC Medium Density"
  rect 1.6x5.3 smd: 1(-2.6,0) 2(2.6,0)
  silkscreen extent -3.69,-2.94 3.69,2.94, body extent -2.95,-2.62 2.95,2.62, height 2.8
2512 [mm] "Chip Resistor, Body 6.3x3.2mm, IPC Medium Density"
  rect 1.3x3.4 smd: 1(-2.95,0) 2(2.95,0)
  silkscreen extent -1.9,-1.6 1.9,1.6, body extent -3.22,-1.67 3.22,1.67, height 0.71
AssemblyNote [mil] "Assembly Note"
CB70-14-CY [mil] "Terminal 90A Lug"
  rect 680x500 hole 262 copper offset -90,0 paste-250: 1(0,0)
  body extent -1300,-260 250,260, height 714
CE_Mark_5mm [mil] "Minimum text height for CE Mark"
  silkscreen extent -138,-98 138,98
CONN_PEC04DAAN [mm] "SULLINS"
  rect 1.65x1.65 hole 1.016 mask+0: 1(-3.81,-1.27)
  round 1.65 hole 1.016 mask+0: 2(-3.81,1.27) 3(-1.27,-1.27) 4(-1.27,1.27) 5(1.27,-1.27) 6(1.27,1.27) 7(3.81,-1.27) 8(3.81,1.27)
  silkscreen extent -6.18,-2.6 5.08,2.54, body extent -5.08,-2.54 5.08,2.54, height 8.38
FCC_disclaimer [mil]
Fiducial10-20 [mm]
  round 1 smd mask+0.5: 1(0,0)
FP-IAUS300N08S5N012ATMA1_HSOG-8-MFG [mm]
  rrect11% 0.9x2.8 smd paste-1000 mask+0: 1(-4.2,-5) 2(-3,-5) 3(-1.8,-5) 4(-0.6,-5) 5(0.6,-5) 6(1.8,-5) 7(3,-5) 8(4.2,-5)
  rrect1% 10.1x8 smd paste-1000 mask-1000: 9(0,2.625)
  silkscreen extent -5.05,-7.53 5.05,-1.75, body extent -5.15,-6.5 5.15,6.73, height 0.25
FP-WSL3921L5000FEA_3921-MFG [mm]
  rrect4% 2.7x6.2 smd paste+0 mask+0: 1(-4.15,0) 2(4.15,0)
  silkscreen extent -2.42,-2.79 2.42,2.79, body extent -5.6,-3.2 5.6,3.2, height 0.25
IEC_HotSurface_Medium [mil]
  silkscreen extent -217,-188 217,188
Keystone5010 [mil] "Keystone Multipurpose loops"
  round 87 hole 63: 1(0,0)
  silkscreen extent -70,-70 70,70, body extent -63,-63 63,62, height 319
Keystone5011 [mil] "Keystone Multipurpose loops"
  round 87 hole 63: 1(0,0)
  silkscreen extent -70,-70 70,70, body extent -63,-63 63,62, height 319
Keystone5012 [mil] "Keystone Multipurpose loops"
  round 87 hole 63: 1(0,0)
  silkscreen extent -70,-70 70,70, body extent -63,-63 63,62, height 319
Keystone5013 [mil] "Keystone Multipurpose loops"
  round 87 hole 63: 1(0,0)
  silkscreen extent -70,-70 70,70, body extent -63,-63 63,62, height 319
Keystone_1902C [mil] "Hex Standoff, 4-40 threaded, nylon"
  round 1 on Mech4: 0(0,0)
  body extent -145,-126 146,126, height 501
LED_LTST-C170_Red [mm] "LITE-ON"
  rect 1.2x1.2 smd: 1(-1.05,0) 2(1.05,0)
  silkscreen extent -1.6,-1 2.2,1, body extent -1.05,-0.67 1.05,0.67, height 1.1
LTST-C170KGKT_Green [mm] "LITE-ON"
  rect 1.2x1.2 smd: 1(-1.05,0) 2(1.05,0)
  silkscreen extent -1.6,-1 2.2,1, body extent -1.05,-0.67 1.05,0.67, height 1.1
NETTIE-SMT2-W0.8L3.3(MM) [mil] "Net-Tie, Surface Mount, 3.3mm x 0.8mm, 2 Pads (2.0 mm x 0.8 mm)"
  rect 78.74x76 smd paste-200 mask-200: 1(-35.08,0.24) 2(16.1,0.24)
"NY PMS 440 0025 PH" [mm] "4-40 nylon screw and mounting hole"
  round 8 hole 3.2 unplated: 1(0,0)
  body extent -3.31,-3.3 3.3,3.3, height 2.69
SM_RADIAL_H13 [mm] "12.5 x 13.5mm:  Panasonic H13"
  rect 5.7x2 smd: 1(-4.85,0) 2(4.85,0)
  silkscreen extent -6.85,-6.85 6.85,6.85, body extent -6.85,-6.85 6.85,6.85, height 14
SM_RADIAL_K16 [mm] "18 x 16.5mm:  Panasonic K16 (K18 from land pattern recommendation)"
  rect 7.5x2.5 smd: 1(-6.75,0) 2(6.75,0)
  silkscreen extent -9.6,-9.6 9.6,9.6, body extent -9.6,-9.6 9.6,9.6, height 17
SMB [mil] "Molded Diode, 2-Leads, Body 5.4x3.6mm, IPC Medium Density, based on OnSemi component dimensions"
  rect 85x107.99 smd: 1(-87.01,0) 2(87.01,0)
  silkscreen extent -155,-82 125,82, body extent -106,-71 106,71, height 91
SMC_265 [mm] "SMD, 2-Leads, Body 7.15x6.25mm"
  rect 2.6x3.2 smd: 1(-3.6,0) 2(3.6,0)
  silkscreen extent -5.6,-3.23 5.3,3.22, body extent -4.08,-3.13 4.08,3.13, height 2.65
SOD-123F [mm] "NXP recommended land pattern"
  rect 1.2x1.2 smd: 1(-1.4,0) 2(1.4,0)
  silkscreen extent -2.64,-1.12 2.01,1.12, body extent -1.8,-0.85 1.8,0.85, height 1.2
SOD-323 [mm] "NXP recommended land pattern"
  rect 0.6x0.6 smd: 1(-1.1,0) 2(1.1,0)
  silkscreen extent -2.06,-0.86 1.53,0.86, body extent -1.3,-0.67 1.3,0.68, height 1.1
SOT-23#1 [mm] "SOT23, 3-Leads, Body 2.9x1.3mm, Pitch 0.95mm, Lead Span 2.5mm, IPC Medium Density"
  rrect50% 1x0.6 smd: 1(-1.2,0.95) 2(-1.2,-0.95) 3(1.2,0)
  silkscreen extent -1.63,-1.5 0.7,1.5, body extent -1.16,-1.45 1.21,1.45, height 1
SOT-23#2 [mm] "SOT23, 3-Leads, Body 2.9x1.3mm, Pitch 0.95mm, Lead Span 2.5mm, IPC Medium Density"
  rect 1.45x0.8 smd: 1(-1.2,0.95) 2(-1.2,-0.95) 3(1.2,0)
  silkscreen extent -1.62,-1.5 0.7,1.5, body extent -1.16,-1.45 1.21,1.45, height 1
SOT-323 [mm] "Diodes Inc recommended land pattern.  2016-02-24"
  rrect21% 0.6x0.47 smd: 1(-0.95,0.65) 2(-0.95,-0.65) 3(0.95,0)
  silkscreen extent -1.14,-1.22 0.78,1.22, body extent -1.13,-1.13 1.12,1.12, height 1.13
SPC02SYAN [mil] "SULLINS"
  round 1 on Mech3: 0(0,0)
  body extent -98,-47 99,47, height 366
Sullins_PEC02DAAN [mil] "Sullins Connector Solutions"
  rect 60x60 hole 40: 1(-50,50)
  round 60 hole 40: 2(50,50) 3(-50,-50) 4(50,-50)
  silkscreen extent -134,-110 110,110, body extent -110,-110 110,110, height 310
SULLINS_PEC03DAAN [mm] "SULLINS"
  rect 1.65x1.65 hole 1.016 mask+0: 1(-2.54,-1.27)
  round 1.65 hole 1.016 mask+0: 2(-2.54,1.27) 3(0,-1.27) 4(0,1.27) 5(2.54,-1.27) 6(2.54,1.27)
  silkscreen extent -4.06,-2.79 3.81,2.54, body extent -3.81,-2.54 3.81,2.54, height 8.38
TI_Stacked_Overlay_Small [mil]
  silkscreen extent -418,-98 418,98
WEEE_Minimum [mil] "WEEElie bin"
  silkscreen extent -95,-172 99,104

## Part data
C1: library part CMP-0008485-2, "CAP, CERM, 0.01 uF, 100 V, +/- 10%, X7R, 1206", Cap_Case=1206, Manufacturer=AVX, Supplier Part Number 1=478-1523-1-ND, TempCo=X7R, Tolerance_%=10%, Value1="0.119 ohm", Value2=100V, ValueDisplayed=0.01uF
C2 C15: library part CMP-0011223-2, "CAP, AL, 220 uF, 100 V, +/- 20%, 0.153 ohm, AEC-Q200 Grade 2, SMD", Cap_Case=K16, Manufacturer=Panasonic, Supplier Part Number 1=PCE3500CT-ND, Tolerance_%=20%, Value1="0.153 ohm", Value2=100V, ValueDisplayed=220uF
C3 C4 C5 C9 C20: library part CMP-0007969-2, "CAP, CERM, 0.1 uF, 100 V, +/- 10%, X7R, AEC-Q200 Grade 1, 0805", Cap_Case=0805, Manufacturer=TDK, Supplier Part Number 1=445-5827-1-ND, TempCo=X7R, Tolerance_%=10%, Value1="0.020726 ohm", Value2=100V, ValueDisplayed=0.1uF
C6 C7: library part CMP-0007092-5, "CAP, CERM, 0.47 uF, 25 V, +/- 10%, X7R, AEC-Q200 Grade 1, 0603", Cap_Case=0603, Manufacturer=TDK, Supplier Part Number 1=445-6929-1-ND, TempCo=X7R, Tolerance_%=10%, Value1=Unknown, Value2=25V, ValueDisplayed=0.47uF
C8: library part CMP-0007711-2, "CAP, CERM, 1000 pF, 50 V, +/- 5%, X7R, 0805", Cap_Case=0805, Manufacturer=Kemet, Supplier Part Number 1=399-1149-1-ND, TempCo=X7R, Tolerance_%=5%, Value1="0.384 ohm", Value2=50V, ValueDisplayed=1000pF
C10: library part CMP-0006687-2, "CAP, CERM, 330 pF, 50 V, +/- 10%, X7R, 0402", Cap_Case=0402, Manufacturer=MuRata, Supplier Part Number 1=490-3247-1-ND, TempCo=X7R, Tolerance_%=10%, Value1=Unknown, Value2=50V, ValueDisplayed=330pF
C11: library part CMP-0860545-1, "CAP, CERM, 1000 pF, 10 V,+/- 10%, X7R, 0402", Cap_Case=0402, Manufacturer=AVX, TempCo=X7R, Tolerance_%=10%, Value2=10V, ValueDisplayed=1000pF
C12: library part CMP-0083622-1, "CAP, CERM, 2.2 µF, 25 V,+/- 10%, X7R, AEC-Q200 Grade 1, 0805", Cap_Case=0805, Manufacturer=MuRata, Supplier Part Number 1=490-4787-1-ND, TempCo=X7R, Tolerance_%=10%, Value2=25V, ValueDisplayed=2.2µF
C13: library part CMP-0007813-2, "CAP, CERM, 0.068 uF, 100 V, +/- 10%, X7R, 0805", Cap_Case=0805, Manufacturer=Kemet, Supplier Part Number 1=399-3484-1-ND, TempCo=X7R, Tolerance_%=10%, Value1="0.078 ohm", Value2=100V, ValueDisplayed=0.068uF
C14: library part CMP-0007814-2, "CAP, CERM, 0.68 uF, 50 V, +/- 10%, X7R, 0805", Cap_Case=0805, Manufacturer=Kemet, Supplier Part Number 1=399-8114-6-ND, TempCo=X7R, Tolerance_%=10%, Value1=Unknown, Value2=50V, ValueDisplayed=0.68uF
C16: library part CMP-0011225-2, "CAP, AL, 47 uF, 100 V, +/- 20%, 0.32 ohm, AEC-Q200 Grade 2, SMD", Cap_Case=H13, Manufacturer=Panasonic, Supplier Part Number 1=PCE3497CT-ND, Tolerance_%=20%, Value1="0.32 ohm", Value2=100V, ValueDisplayed=47uF
C17 C18: library part CMP-0009354-2, "CAP, CERM, 1 uF, 100 V, +/- 10%, X7R, 1812", Cap_Case=1812_254, Manufacturer=TDK, Supplier Part Number 1=445-1438-1-ND, TempCo=X7R, Tolerance_%=10%, Value1="0.005865 ohm", Value2=100V, ValueDisplayed=1uF
C19: library part CMP-0007542-2, "CAP, CERM, 0.01 uF, 100 V, +/- 5%, X7R, 0805", Cap_Case=0805, Manufacturer=AVX, Supplier Part Number 1=478-3745-1-ND, TempCo=X7R, Tolerance_%=5%, Value1="0.078 ohm", Value2=100V, ValueDisplayed=0.01uF
C21: library part CMP-0009304-2, "CAP, CERM, 10 uF, 100 V, +/- 20%, X7R, 2220", Cap_Case=2220, Manufacturer=AVX, Supplier Part Number 1=478-9622-1-ND, TempCo=X7R, Tolerance_%=20%, Value1=Unknown, Value2=100V, ValueDisplayed=10uF
D1: library part CMP-0005734-3, "Diode, TVS, Uni, 70 V, 113 Vc, SMC", Manufacturer=Littelfuse, Value1=1500W
D2: library part CMP-0028987-2, "Diode, Schottky, 100 V, 2 A, SMB", Manufacturer=Vishay-Semiconductor, Value1=2A, Value2=0.79V
D3: library part CMP-0002888-1, "LED, Green, SMD", Color=Green, Manufacturer=Lite-On, Supplier Part Number 1=160-1414-1-ND, Value1=W, Value2=2V
D4 D5: library part CMP-0002829-3, "LED, Red, SMD", Color=red, Manufacturer=Lite-On, Value1=W, Value2=2V
D6: library part CMP-0085742-1, "Diode, Zener, 5.6 V, 300 mW, AEC-Q101, SOD-323", Manufacturer="ON Semiconductor", Power_W=300mW, Value1=0.3W
D10 D11: library part CMP-0028632-2, "Diode, Schottky, 100 V, 0.25 A, SOD-123F", Manufacturer=Nexperia, Value1=0.25A, Value2=0.85V
FID1 FID2 FID3 FID4 FID5 FID6: library part CMP-0077181-1, "Fiducial mark.  There is nothing to buy or mount.", Manufacturer=N/A
H1 H2 H3 H4: library part CMP-0003617-1, "Machine Screw, Round, #4-40 x 1/4, Nylon, Philips panhead", Manufacturer="B&F Fastener Supply", Supplier Part Number 1=H542-ND
H5 H6 H7 H8: library part CMP-0003610-1, Manufacturer=Keystone, Supplier Part Number 1=36-1902C-ND
J1: library part CMP-0054552-1, "Header, 100mil, 3x2, Tin, TH", Color=Black, Current_A=3A, Manufacturer="Sullins Connector Solutions", Supplier Part Number 1=S2012E-03-ND, Voltage_V=1.8kV
J2: library part CMP-0054558-1, "Header, 100mil, 2x2, Tin, TH", Manufacturer="Sullins Connector Solutions", Supplier Part Number 1=S2012E-02-ND
J3: library part CMP-0054542-1, "Header, 100mil, 4x2, Tin, TH", Color=Black, Current_A=3A, Manufacturer="Sullins Connector Solutions", Supplier Part Number 1=S2012E-04-ND, Voltage_V=1.8kV
Logo1: library part CMP-0074838-1, "Texas Instrument Corporate Signature"
Logo2: library part CMP-0074847-1, "FCC_disclaimer"
Logo3: library part CMP-0074769-1
LOGO4: library part CMP-0074844-1
LOGO6: library part CMP-0074837-1, "IEC 61010-1 Hot Surface Warning"
NT1 NT2: library part CMP-0494-00001-2, "Net-Tie, Surface Mount, 3.3 mm x 0.8 mm, 2 Pads (2.0 mm x 0.8 mm)", Manufacturer="No Vendor"
Q1 Q2 Q3 Q12 Q13 Q14: library part CMP-0089282-1, "N-Channel 80V 300A (Tc) 375W (Tc) Surface Mount PG-HSOG-8-1", Digikey Part Number=IAUS300N08S5N012ATMA1CT-ND, Drain To Source Breakdown Voltage=80V, Input Capacitace At Vds="12500pF @ 40V", Manufacturer=Infineon, Mouser Part Number=726-IAUS300N08S5N012, Operating Temperature Range="-55°C to +175°C", Power_W=375W, Pulse Drain Current=1200A, Typ Forward Diode Voltage=0.9V
Q4 Q16: library part CMP-0000776-1, "MOSFET, N-CH, 60 V, 0.115 A, SOT-323", Alternate Manufacturer=None, Manufacturer="Diodes Inc.", Supplier Part Number 1=2N7002W-FDICT-ND, Value1=7
Q5: library part CMP-0750056-1, "Transistor, NPN, 160 V, 0.3 A, SOT-23", Manufacturer=Nexperia, Value1="0.3 A", Value2=250
Q6: library part CMP-0000386-2, "Transistor, NPN, 40 V, 0.2 A, SOT-23", Manufacturer="Fairchild Semiconductor", Supplier Part Number 1=MMBT3904FSCT-ND, Value1="0.2 A", Value2=300
Q15: library part CMP-0000971-2, "MOSFET, N-CH, 100 V, 1.4 A, SOT-23", Alternate Manufacturer=None, Manufacturer="Diodes Inc.", Supplier Part Number 1=DMN10H220L-7DICT-ND, Value1=0.2, Value2="4.1 nC"
R1 R2: library part CMP-0092921-1, "Res Metal Strip 3921 0.0005 Ohm 1% 3W ±175ppm/°C Molded SMD SMD Embossed Plastic T/R", Digikey Part Number=WSLM-.0005CT-ND, Manufacturer="Vishay Dale", Mouser Part Number=71-WSL3921L5000FEA, Operating Temperature Range="-65°C to +170°C", Power_W=3W, TempCo=150ppm/°C, Tolerance_%=1%
R3: library part CMP-0016570-3, "RES, 100, 1%, 0.5 W, AEC-Q200 Grade 0, 1206", Manufacturer=Vishay-Dale, Power_W=500mW, Supplier Part Number 1=541-100UCT-ND, TempCo="100 ppm/C", Tolerance_%=1%, Value2=0.5W, Value_Code=100R, ValueDisplayed=100
R4 R7: library part CMP-0015538-3, "RES, 220, 1%, 1 W, AEC-Q200 Grade 0, 2512", Manufacturer=Vishay-Dale, Power_W=1W, Supplier Part Number 1=541-220AFCT-ND, TempCo="100 ppm/C", Tolerance_%=1%, Value_Code=220R, ValueDisplayed=220
R5: library part CMP-0020835-3, "RES, 100, 1%, 0.125 W, AEC-Q200 Grade 0, 0805", Manufacturer=Vishay-Dale, Power_W=125mW, Supplier Part Number 1=541-100CCT-ND, TempCo="100 ppm/C", Tolerance_%=1%, Value2=0.125W, Value_Code=100R, ValueDisplayed=100
R6 R8 R41 R45: library part CMP-0023007-4, "RES, 2.21, 1%, 0.1 W, 0603", Manufacturer=Yageo, Power_W=100mW, Supplier Part Number 1=311-2.21HRCT-ND, TempCo="200 ppm/C", Tolerance_%=1%, Value2=0.1W, Value_Code=2R21, ValueDisplayed=2.21
R9 R13 R43: library part CMP-0025697-4, "RES, 0, 5%, 0.1 W, AEC-Q200 Grade 0, 0603", Manufacturer=Vishay-Dale, Power_W=100mW, Supplier Part Number 1=541-0.0GCT-ND, TempCo="200 ppm/C", Tolerance_%=5%, Value2=0.1W, Value_Code=0000, ValueDisplayed=0
R10: library part CMP-0022004-4, "RES, 10.0, 1%, 0.25 W, AEC-Q200 Grade 0, 0603", Manufacturer=Vishay-Dale, Power_W=250mW, Supplier Part Number 1=541-10.0SCT-ND, TempCo="100 ppm/C", Tolerance_%=1%, Value2=0.25W, Value_Code=10R0, ValueDisplayed=10.0
R11 R17 R30 R31 R49: library part CMP-0023335-5, "RES, 9.53 k, 1%, 0.1 W, 0603", Manufacturer=Yageo, Power_W=100mW, Supplier Part Number 1=311-9.53KHRCT-ND, TempCo="100 ppm/C", Tolerance_%=1%, Value2=0.1W, Value_Code=9k53, ValueDisplayed=9.53k
R12 R21 R22 R47: library part CMP-0022373-4, "RES, 3.16 k, 1%, 0.1 W, AEC-Q200 Grade 0, 0603", Manufacturer=Vishay-Dale, Power_W=100mW, Supplier Part Number 1=541-3.16KHCT-ND, TempCo="100 ppm/C", Tolerance_%=1%, Value2=0.1W, Value_Code=3k16, ValueDisplayed=3.16k
R14: library part CMP-0023892-3, "RES, 1.47 k, 0.1%, 0.1 W, 0603", Manufacturer="Yageo America", Power_W=100mW, TempCo="25 ppm/C", Tolerance_%=0.1%, Value2=0.1W, Value_Code=1k47, ValueDisplayed=1.47k
R15: library part CMP-0021863-2, "RES, 10.0, 1%, 0.125 W, 0805", Manufacturer="Yageo America", Power_W=125mW, Supplier Part Number 1=311-10.0CRCT-ND, TempCo="200 ppm/C", Tolerance_%=1%, Value2=0.125W, Value_Code=10R0, ValueDisplayed=10.0
R16 R42: library part CMP-0023128-4, "RES, 470 k, 1%, 0.1 W, 0603", Manufacturer=Yageo, Power_W=100mW, Supplier Part Number 1=311-470KHRCT-ND, TempCo="100 ppm/C", Tolerance_%=1%, Value2=0.1W, Value_Code=470k
R18 R19 R20: library part CMP-0021520-3, "RES, 10.0 k, 1%, 0.125 W, AEC-Q200 Grade 0, 0805", Manufacturer=Panasonic, Power_W=125mW, Supplier Part Number 1=P10.0KCCT-ND, TempCo="100 ppm/C", Tolerance_%=1%, Value2=0.125W, Value_Code=10k0, ValueDisplayed=10.0k
R23: library part CMP-0021990-4, "RES, 100 k, 1%, 0.1 W, AEC-Q200 Grade 0, 0603", Manufacturer=Vishay-Dale, Power_W=100mW, Supplier Part Number 1=541-100KHCT-ND, TempCo="100 ppm/C", Tolerance_%=1%, Value2=0.1W, Value_Code=100k
R24: library part CMP-0023102-5, "RES, 41.2 k, 1%, 0.1 W, 0603", Manufacturer=Yageo, Power_W=100mW, Supplier Part Number 1=311-41.2KHRCT-ND, TempCo="100 ppm/C", Tolerance_%=1%, Value2=0.1W, Value_Code=41k2, ValueDisplayed=41.2k
R25: library part CMP-0024922-3, "RES, 20.0 k, 0.5%, 0.1 W, 0603", Manufacturer="Yageo America", Power_W=100mW, TempCo="50 ppm/C", Tolerance_%=0.5%, Value2=0.1W, Value_Code=20k0, ValueDisplayed=20.0k
R26 R48: library part CMP-0025874-2, "RES, 0, 5%, 0.1 W, 0603", Manufacturer=Panasonic, Power_W=100mW, Supplier Part Number 1=P0.0GCT-ND, TempCo="600 ppm/C", Tolerance_%=5%, Value2=0.1W, Value_Code=0000, ValueDisplayed=0
R27: library part CMP-0023130-4, "RES, 475 k, 1%, 0.1 W, 0603", Manufacturer=Yageo, Power_W=100mW, Supplier Part Number 1=311-475KHRCT-ND, TempCo="100 ppm/C", Tolerance_%=1%, Value2=0.1W, Value_Code=475k
R28: library part CMP-0022064-4, "RES, 158 k, 1%, 0.1 W, AEC-Q200 Grade 0, 0603", Manufacturer=Vishay-Dale, Power_W=100mW, Supplier Part Number 1=541-158KHCT-ND, TempCo="100 ppm/C", Tolerance_%=1%, Value2=0.1W, Value_Code=158k
R29: library part CMP-0022438-4, "RES, 47.0 k, 1%, 0.1 W, AEC-Q200 Grade 0, 0603", Manufacturer=Vishay-Dale, Power_W=100mW, Supplier Part Number 1=541-47.0KHCT-ND, TempCo="100 ppm/C", Tolerance_%=1%, Value2=0.1W, Value_Code=47k0, ValueDisplayed=47.0k
R44: library part CMP-0021075-3, "RES, 24.9 k, 1%, 0.125 W, AEC-Q200 Grade 0, 0805", Manufacturer=Vishay-Dale, Power_W=125mW, Supplier Part Number 1=541-24.9KCCT-ND, TempCo="100 ppm/C", Tolerance_%=1%, Value2=0.125W, Value_Code=24k9, ValueDisplayed=24.9k
SH-J1 SH-J2 SH-J3: library part CMP-0003642-1, "Shunt, 100mil, Flash Gold, Black", Manufacturer="Sullins Connector Solutions", PartNumber=SPC02SYAN, Supplier Part Number 1=S9001-ND
T1 T2 T3 T4: library part CMP-0055443-2, "Terminal 90A Lug", Manufacturer=Panduit, Supplier Part Number 1=CB70-14-CY-ND, Voltage_V=600V
TP1 TP2 TP9: library part CMP-0055147-1, "Test Point, Multipurpose, Red, TH", Color=Red, Manufacturer=Keystone, PartNumber=5010, Supplier Part Number 1=36-5010-ND
TP3 TP5 TP6 TP8 TP10 TP11 TP12 TP13 TP14 TP24 TP25: library part CMP-0055149-1, "Test Point, Multipurpose, White, TH", Color=White, Manufacturer=Keystone, PartNumber=5012, Supplier Part Number 1=36-5012-ND
TP7 TP26: library part CMP-0055150-1, "Test Point, Multipurpose, Orange, TH", Color=Orange, Manufacturer=Keystone, PartNumber=5013, Supplier Part Number 1=36-5013-ND
TP15 TP16 TP17 TP18: library part CMP-0055148-1, "Test Point, Multipurpose, Black, TH", Color=Black, Manufacturer=Keystone, PartNumber=5011, Supplier Part Number 1=36-5011-ND
U2: library part CMP-0092088-1, "100V Smart High Side controller with Protection and Diagnostics", Manufacturer="Texas Instruments", Max Supply Voltage=80V, Min Supply Voltage=3.5V, Nominal Supply Current=1uA, Operating Temperature Range=to
ZZ1: library part CMP-0077236-1
ZZ2: library part CMP-0077237-1
ZZ3: library part CMP-0077238-1

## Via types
v1: diameter 24, hole 12, L1-Top Layer to L4-Bottom Layer, 863 vias
v2: diameter 32, hole 16, L1-Top Layer to L4-Bottom Layer, 232 vias
v3: diameter 20, hole 10, L1-Top Layer to L4-Bottom Layer, 15 vias

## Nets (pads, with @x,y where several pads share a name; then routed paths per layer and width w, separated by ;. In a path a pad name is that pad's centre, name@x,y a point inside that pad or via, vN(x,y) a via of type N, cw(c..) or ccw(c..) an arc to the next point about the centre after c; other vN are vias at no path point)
BST: C6.1 C7.1 U2.12 | length 252.3
  L1-Top Layer w12: U2.12@1932.64,2089.62 1932.64,2043.53 1943.81,2032.36
  L1-Top Layer w20: 1943.81,2032.36 1956.15,2020.02 1991.27,2020.02 2007.62,2036.37 C6.1@2007.62,2086.25 C7.1@2072.41,2086.25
